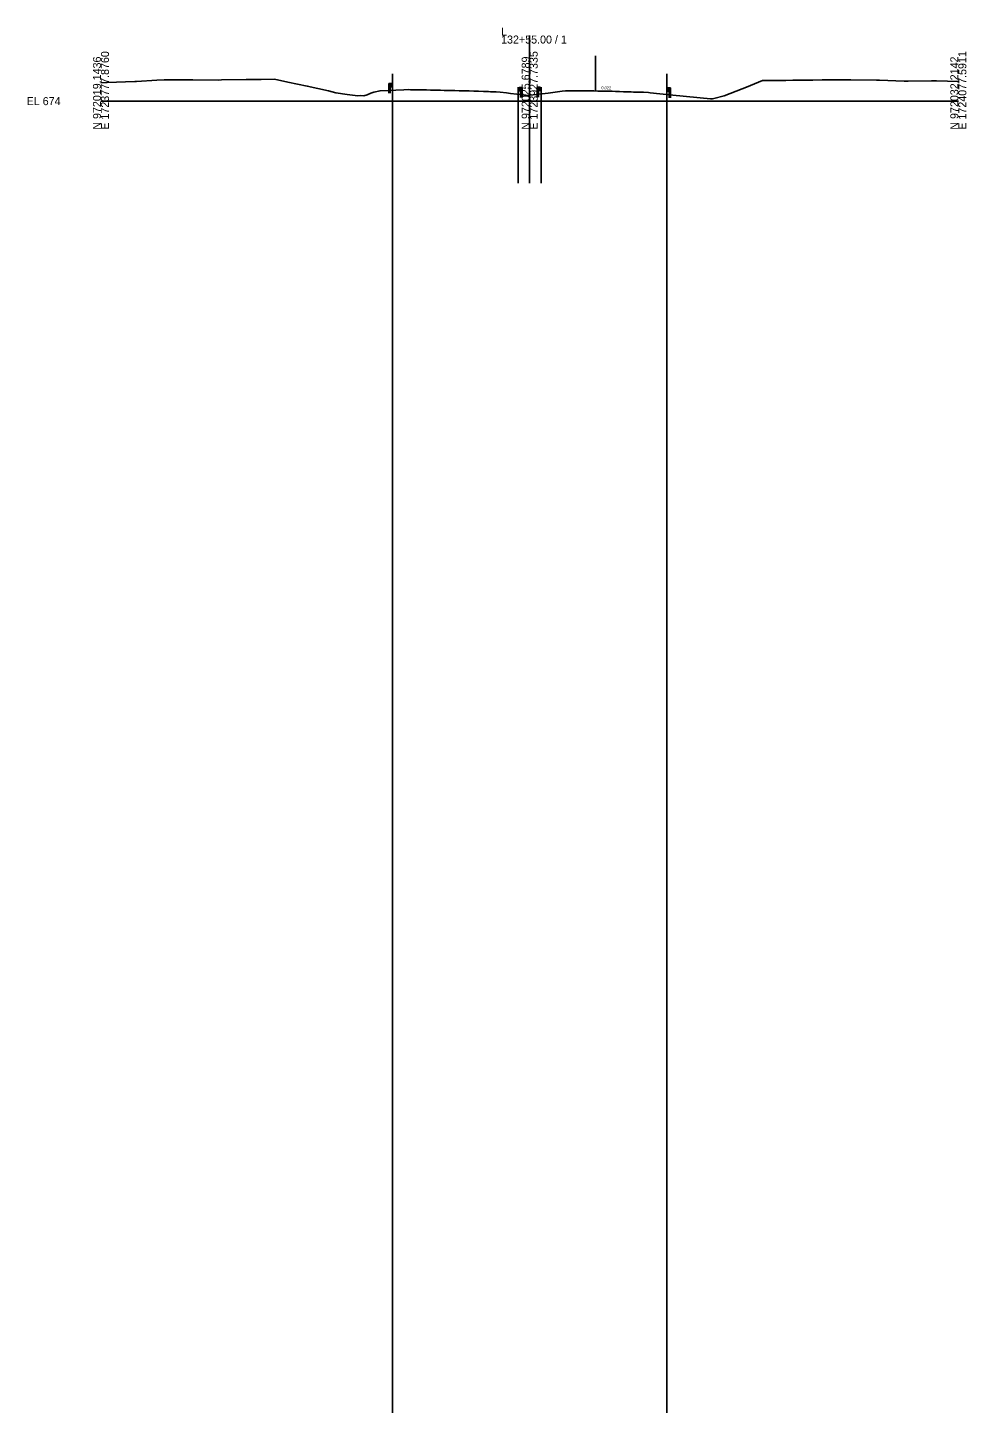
# Model space of a CAD drawing. Extents: x -26 to 303, y -29 to 15026.
# Drawn here: x -25.7 to 302.8, y 14544.2 to 15025.8 of the extents above; entities that cross this region are included whole.
import ezdxf

# ---------------------------------------------------------------- set-up
doc = ezdxf.new("R2010")
doc.units = 0
for name, color, linetype in [('Exist Cross Section Cell', 7, 'Continuous'), ('Exist XS Center Line Elevation Label', 7, 'Continuous'), ('Exist XS Ground Line', 7, 'Continuous'), ('Prop XS Ditch Standard Text', 7, 'Continuous'), ('Scratch_Level_0', 7, 'Continuous'), ('Typical Guardrail CELL', 7, 'Continuous')]:
    doc.layers.add(name, color=color, linetype=linetype)

msp = doc.modelspace()

# ---------------------------------------------------------------- linework, layer by layer
at = {"layer": 'Exist Cross Section Cell'}
for p, q in [((150, 15000), (150, 15022.96)), ((0, 15000), (150, 15000)), ((150, 15000), (300, 15000))]:
    msp.add_line(p, q, dxfattribs=at)
at = {"layer": 'Exist XS Ground Line'}
msp.add_lwpolyline([(0, 15006.43), (2.14, 15006.51), (11.81, 15006.85), (12.15, 15006.86), (12.46, 15006.86), (19.53, 15007.3), (22.16, 15007.45), (31.64, 15007.48), (32.17, 15007.49), (41.23, 15007.37), (42.18, 15007.4), (50.82, 15007.58), (52.18, 15007.61), (56.08, 15007.58), (60.67, 15007.65), (65.42, 15006.62), (72.2, 15005.29), (79.59, 15003.55), (82.21, 15002.95), (86.12, 15002.34), (89.83, 15001.8), (90.85, 15001.97), (91.96, 15001.85), (93.11, 15002.18), (94.38, 15002.77), (95.52, 15003.16), (97.67, 15003.62), (105.96, 15003.94), (107.62, 15004.02), (108.33, 15004.01), (108.84, 15004.01), (110.72, 15004), (111.37, 15003.99), (112.12, 15003.97), (113.85, 15003.91), (115.32, 15003.89), (116.35, 15003.88), (117.47, 15003.85), (118.85, 15003.81), (120.11, 15003.77), (121.34, 15003.74), (122.37, 15003.72), (123.13, 15003.7), (123.83, 15003.69), (125.28, 15003.66), (126.32, 15003.63), (127.89, 15003.59), (128.82, 15003.57), (130.52, 15003.52), (131.33, 15003.5), (132.07, 15003.47), (133.84, 15003.42), (135.28, 15003.36), (135.62, 15003.35), (136.35, 15003.31), (136.81, 15003.29), (137.66, 15003.26), (138.23, 15003.24), (139.66, 15003.09), (141.88, 15002.85), (143.24, 15002.7), (145.55, 15002.46), (149.71, 15002.02), (150.13, 15002.07), (156.47, 15002.79), (161.38, 15003.43), (162.53, 15003.57), (163.14, 15003.58), (164.26, 15003.59), (165.61, 15003.59), (166.4, 15003.58), (167.18, 15003.58), (168.89, 15003.57), (170.48, 15003.57), (171.41, 15003.56), (172.4, 15003.55), (173.89, 15003.54), (175.26, 15003.52), (176.4, 15003.51), (176.76, 15003.5), (177.06, 15003.49), (177.75, 15003.47), (178.88, 15003.43), (180.03, 15003.39), (181.38, 15003.35), (182.83, 15003.31), (183.87, 15003.29), (185.47, 15003.23), (186.38, 15003.19), (187.23, 15003.17), (188.76, 15003.12), (189.35, 15003.1), (189.89, 15003.08), (191.6, 15002.99), (192.21, 15002.95), (195.5, 15002.58), (200.11, 15002.06), (213.33, 15000.86), (213.97, 15000.82), (214.48, 15000.93), (218.1, 15001.83), (226.42, 15005.14), (227.28, 15005.48), (228.64, 15006.04), (231.5, 15007.17), (239.61, 15007.26), (242.03, 15007.28), (242.63, 15007.29), (249.05, 15007.38), (252.36, 15007.43), (261.82, 15007.44), (262.37, 15007.44), (271.41, 15007.38), (272.38, 15007.35), (281, 15007.01), (282.39, 15006.99), (290.59, 15007.11), (292.4, 15007.12), (300, 15006.91)], dxfattribs=at)
at = {"layer": 'Scratch_Level_0'}
for p, q in [((173, 15015.8), (173, 15003.55)), ((102, 15009.56), (102, -28.7)), ((198, 15009.56), (198, -28.7)), ((146.03, 15004.86), (146.03, 14971.3)), ((153.97, 15004.86), (153.97, 14971.3)), ((173, 15003.55), (180.03, 15003.39)), ((150, 15000), (150, 14971.3))]:
    msp.add_line(p, q, dxfattribs=at)
at = {"layer": 'Typical Guardrail CELL'}
for p, q in [((101.18, 15006.22), (100.68, 15006.22)), ((100.68, 15006.22), (100.68, 15003.74)), ((101.18, 15006.22), (101.18, 15003.74)), ((101.18, 15006.22), (101.68, 15006.22)), ((101.68, 15006.22), (101.68, 15005.06)), ((101.68, 15006.22), (101.97, 15006.02)), ((101.68, 15005.69), (101.97, 15005.89)), ((101.68, 15005.64), (101.68, 15005.69)), ((101.68, 15005.64), (101.68, 15005.6)), ((101.68, 15005.6), (101.97, 15005.39)), ((101.18, 15003.74), (100.68, 15003.74)), ((100.68, 15003.74), (100.68, 15002.73)), ((101.18, 15005.06), (101.68, 15005.06)), ((101.18, 15003.74), (101.18, 15002.73)), ((101.68, 15005.06), (101.97, 15005.27)), ((146.35, 15004.76), (146.06, 15004.55)), ((146.35, 15004.22), (146.06, 15004.43)), ((146.35, 15004.13), (146.06, 15003.93)), ((146.35, 15003.6), (146.06, 15003.8)), ((146.85, 15004.76), (146.35, 15004.76)), ((146.35, 15004.76), (146.35, 15003.6)), ((146.35, 15004.18), (146.35, 15004.22)), ((146.35, 15004.18), (146.35, 15004.13)), ((146.85, 15003.6), (146.35, 15003.6)), ((146.85, 15004.76), (146.85, 15002.27)), ((146.85, 15004.76), (147.35, 15004.76)), ((146.85, 15002.27), (147.35, 15002.27)), ((146.85, 15002.27), (146.85, 15001.26)), ((147.35, 15004.76), (147.35, 15002.27)), ((147.35, 15002.27), (147.35, 15001.26)), ((153.15, 15004.84), (152.65, 15004.84)), ((152.65, 15004.84), (152.65, 15002.35)), ((153.15, 15002.35), (152.65, 15002.35)), ((152.65, 15002.35), (152.65, 15001.34)), ((153.15, 15004.84), (153.15, 15002.35)), ((153.15, 15004.84), (153.65, 15004.84)), ((153.15, 15003.68), (153.65, 15003.68)), ((153.15, 15002.35), (153.15, 15001.34)), ((153.65, 15004.84), (153.65, 15003.68)), ((153.65, 15004.84), (153.94, 15004.64)), ((153.65, 15004.31), (153.94, 15004.51)), ((153.65, 15004.26), (153.65, 15004.31)), ((153.65, 15004.26), (153.65, 15004.21)), ((153.65, 15004.21), (153.94, 15004.01)), ((153.65, 15003.68), (153.94, 15003.88)), ((198.32, 15004.63), (198.03, 15004.43)), ((198.32, 15004.1), (198.03, 15004.3)), ((198.32, 15004.01), (198.03, 15003.8)), ((198.32, 15003.47), (198.03, 15003.68)), ((198.82, 15004.63), (198.32, 15004.63)), ((198.32, 15004.63), (198.32, 15003.47)), ((198.32, 15004.05), (198.32, 15004.1)), ((198.32, 15004.05), (198.32, 15004.01)), ((198.82, 15003.47), (198.32, 15003.47)), ((198.82, 15004.63), (198.82, 15002.15)), ((198.82, 15004.63), (199.32, 15004.63)), ((198.82, 15002.15), (199.32, 15002.15)), ((198.82, 15002.15), (198.82, 15001.14)), ((199.32, 15004.63), (199.32, 15002.15)), ((199.32, 15002.15), (199.32, 15001.14))]:
    msp.add_line(p, q, dxfattribs=at)
for centre, start, end in [((101.92, 15005.96), 304.9888, 54.997), ((101.92, 15005.33), 304.9634, 54.9941), ((146.11, 15004.49), 125.003, 235.0112), ((146.11, 15003.86), 125.0059, 235.0366), ((153.89, 15004.57), 304.9888, 54.997), ((153.89, 15003.95), 304.9634, 54.9941), ((198.08, 15004.37), 125.003, 235.0112), ((198.08, 15003.74), 125.0059, 235.0366)]:
    msp.add_arc(centre, 0.0776, start, end, dxfattribs=at)

# ---------------------------------------------------------------- texts
at = {"layer": 'Exist Cross Section Cell'}
for s, p in [('L', (140, 15022.96)), ('132+55.00 / 1', (140, 15020.16)), ('EL 674', (-26, 14998.6))]:
    msp.add_text(s, height=2.8, dxfattribs=at).set_placement(p)
for s, p in [('N 972019.1436', (0, 14990)), ('E 1723777.8760', (2.8, 14990)), ('N 972025.6789', (150, 14990)), ('E 1723927.7335', (152.8, 14990)), ('N 972032.2142', (300, 14990)), ('E 1724077.5911', (302.8, 14990))]:
    msp.add_text(s, height=2.8, rotation=90, dxfattribs=at).set_placement(p)
at = {"layer": 'Exist XS Center Line Elevation Label'}
msp.add_text('676.05', height=0.18, dxfattribs=at).set_placement((149.62, 15001.56))
at = {"layer": 'Prop XS Ditch Standard Text'}
msp.add_text('0.022', height=1, rotation=358.7294, dxfattribs=at).set_placement((175.06, 15004.18))

doc.saveas('drawing.dxf')
